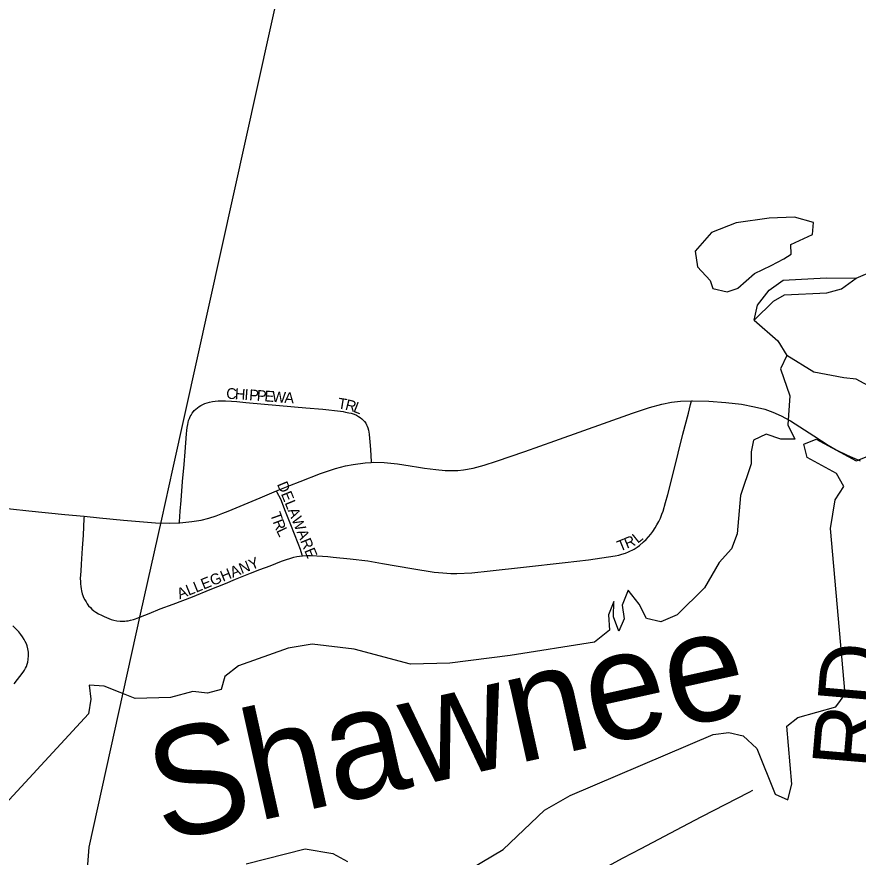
# Model space of a CAD drawing. Extents: x -49 to -8.2, y 9.4 to 23.5.
# Drawn here: x -45.4614 to -45.0943, y 18.5589 to 18.9257 of the extents above; entities that cross this region are included whole.
import ezdxf

# ---------------------------------------------------------------- set-up
doc = ezdxf.new("R2010")
doc.units = 0
for name, color, linetype in [('GM_X_County_Road_Text', 7, 'Continuous'), ('GM_X_Major_Lake', 7, 'Continuous'), ('GM_X_Major_Lake_Text', 7, 'Continuous'), ('GM_X_Major_River', 7, 'Continuous'), ('GM_X_Minor_Lake', 7, 'Continuous'), ('GM_X_Township', 7, 'Continuous'), ('GM_X_Township_Road', 7, 'Continuous'), ('GM_X_Township_Subdivision', 7, 'Continuous'), ('GM_X_Township_Subdivision_Text', 7, 'Continuous')]:
    doc.layers.add(name, color=color, linetype=linetype)

msp = doc.modelspace()

# ---------------------------------------------------------------- linework, layer by layer
at = {"layer": 'GM_X_Major_Lake'}
for points in [[(-45.08824, 18.76383), (-45.09517, 18.76759), (-45.10047, 18.76809), (-45.11368, 18.77065), (-45.12546, 18.77793), (-45.12824, 18.77211), (-45.12414, 18.76026), (-45.125, 18.74756), (-45.12191, 18.74142), (-45.12798, 18.74137), (-45.13437, 18.7436), (-45.13993, 18.74087), (-45.14099, 18.73577), (-45.14092, 18.73065), (-45.14559, 18.71671), (-45.1471, 18.70005), (-45.14952, 18.69346), (-45.15496, 18.68751), (-45.16127, 18.67645), (-45.17328, 18.66476), (-45.18036, 18.66169), (-45.18659, 18.66316), (-45.18986, 18.6693), (-45.19465, 18.67548), (-45.19726, 18.66889), (-45.19645, 18.66299), (-45.19865, 18.65754), (-45.20098, 18.66385), (-45.20083, 18.67049), (-45.20323, 18.66466), (-45.20281, 18.65801), (-45.20937, 18.65284), (-45.24609, 18.64701), (-45.27251, 18.64361), (-45.28958, 18.64322), (-45.31427, 18.64965), (-45.3326, 18.65195), (-45.34307, 18.65009), (-45.36466, 18.6424), (-45.37064, 18.63779), (-45.37228, 18.63214), (-45.37819, 18.63056), (-45.38462, 18.63127), (-45.39435, 18.62864), (-45.40971, 18.62822), (-45.41629, 18.63083), (-45.42324, 18.63364), (-45.42987, 18.63397), (-45.42905, 18.62788), (-45.43014, 18.62146), (-45.47521, 18.57274)], [(-45.10629, 18.70238), (-45.10431, 18.71486), (-45.10057, 18.72065), (-45.10367, 18.72641), (-45.11659, 18.73334), (-45.11798, 18.73925), (-45.11262, 18.74141), (-45.09521, 18.73192), (-45.08966, 18.73408)], [(-45.26775, 18.55129), (-45.24912, 18.56227), (-45.2311, 18.57952), (-45.21997, 18.58591), (-45.15758, 18.61243), (-45.15073, 18.61342), (-45.14451, 18.61196), (-45.13857, 18.60632), (-45.13049, 18.58641), (-45.12504, 18.58402), (-45.12318, 18.59081), (-45.12546, 18.61609), (-45.12064, 18.61997), (-45.10405, 18.62454), (-45.09994, 18.63014), (-45.10629, 18.70238)], [(-45.36128, 18.556), (-45.33554, 18.56265), (-45.32346, 18.56048), (-45.31709, 18.55712)]]:
    msp.add_lwpolyline(points, dxfattribs=at)
at = {"layer": 'GM_X_Major_River'}
for points in [[(-45.09514, 18.81161), (-45.07839, 18.81872)], [(-45.13971, 18.79323), (-45.13824, 18.79984), (-45.13316, 18.80637), (-45.127, 18.81079), (-45.10821, 18.8117), (-45.09514, 18.81161)], [(-45.13971, 18.79323), (-45.13118, 18.80158), (-45.12638, 18.80432), (-45.10798, 18.80525), (-45.10149, 18.807), (-45.09514, 18.81161)], [(-45.13971, 18.79323), (-45.1293, 18.78428), (-45.12544, 18.77792)]]:
    msp.add_lwpolyline(points, dxfattribs=at)
at = {"layer": 'GM_X_Minor_Lake'}
for points in [[(-45.13955, 18.81366), (-45.1323, 18.81716), (-45.12675, 18.82011), (-45.1235, 18.82215), (-45.12362, 18.82633), (-45.11427, 18.83074), (-45.11381, 18.83586), (-45.12211, 18.83826), (-45.13312, 18.83786), (-45.14756, 18.8358), (-45.15824, 18.8316), (-45.16538, 18.82336), (-45.16435, 18.81651), (-45.15894, 18.81054), (-45.15767, 18.80711), (-45.15143, 18.80568), (-45.14667, 18.80732)], [(-45.14673, 18.8073), (-45.13955, 18.81366)]]:
    msp.add_lwpolyline(points, dxfattribs=at)
at = {"layer": 'GM_X_Township'}
for points in [[(-45.45858, 18.19023), (-45.4371, 18.46983), (-45.42991, 18.5633), (-45.40738, 18.66501), (-45.3982, 18.70644), (-45.39337, 18.72821), (-45.30298, 19.13613), (-45.29363, 19.17835), (-45.29186, 19.18634), (-45.28927, 19.19802), (-45.28163, 19.23249), (-45.27701, 19.25333), (-45.23827, 19.42819), (-45.23665, 19.48739)], [(-45.45858, 18.19023), (-45.4371, 18.46983), (-45.42991, 18.5633), (-45.40738, 18.66501), (-45.3982, 18.70644), (-45.39337, 18.72821), (-45.30298, 19.13613), (-45.29363, 19.17835), (-45.29186, 19.18634), (-45.28927, 19.19802), (-45.28163, 19.23249), (-45.27701, 19.25333), (-45.23827, 19.42819), (-45.18647, 19.42522), (-44.37214, 19.37853)]]:
    msp.add_lwpolyline(points, dxfattribs=at)
at = {"layer": 'GM_X_Township_Road'}
for points in [[(-45.30676, 18.73125), (-45.30574, 18.73131), (-45.30115, 18.73113), (-45.29531, 18.7306), (-45.28983, 18.72979), (-45.2862, 18.72919), (-45.28346, 18.72878), (-45.27855, 18.72807), (-45.27453, 18.72771), (-45.27109, 18.72765), (-45.26893, 18.72774), (-45.26645, 18.72799), (-45.26229, 18.72875), (-45.25747, 18.72999), (-45.25215, 18.73172), (-45.23981, 18.73598), (-45.22662, 18.74057), (-45.19269, 18.7527), (-45.18534, 18.75516), (-45.17999, 18.75668), (-45.17577, 18.75752), (-45.17179, 18.75795), (-45.167, 18.75807)], [(-45.167, 18.75807), (-45.16655, 18.75809), (-45.15943, 18.75792), (-45.15201, 18.7574), (-45.14525, 18.75657), (-45.13947, 18.75553), (-45.13499, 18.75441), (-45.1315, 18.75322), (-45.12787, 18.75157), (-45.12384, 18.7493), (-45.11368, 18.74277), (-45.10738, 18.73874), (-45.10386, 18.73673), (-45.09911, 18.73436), (-45.09335, 18.73195)], [(-45.34804, 18.71877), (-45.34232, 18.72112), (-45.33774, 18.72294), (-45.32884, 18.72637), (-45.3224, 18.72851), (-45.31792, 18.72966), (-45.3146, 18.73033), (-45.30941, 18.73107), (-45.30676, 18.73125)], [(-45.3905, 18.70487), (-45.39029, 18.70487), (-45.385, 18.70537), (-45.38098, 18.70603), (-45.37763, 18.70686), (-45.37437, 18.70794), (-45.37148, 18.70907), (-45.36918, 18.70999), (-45.35519, 18.71583), (-45.34804, 18.71877)], [(-45.51521, 18.70597), (-45.51161, 18.7082), (-45.50831, 18.70985), (-45.5049, 18.71123), (-45.50199, 18.71214), (-45.49808, 18.7129), (-45.49412, 18.71335), (-45.49107, 18.71342), (-45.48399, 18.71285), (-45.47566, 18.71201), (-45.46421, 18.71092), (-45.45619, 18.71011), (-45.44047, 18.70855), (-45.43209, 18.7077)], [(-45.43209, 18.7077), (-45.42534, 18.70702), (-45.41479, 18.70601)], [(-45.41479, 18.70601), (-45.40957, 18.70551), (-45.40089, 18.70487), (-45.39497, 18.70473), (-45.3905, 18.70487)]]:
    msp.add_lwpolyline(points, dxfattribs=at)
at = {"layer": 'GM_X_Township_Subdivision'}
for points in [[(-45.3905, 18.70487), (-45.39047, 18.70523), (-45.39009, 18.70992), (-45.38971, 18.71467), (-45.38905, 18.72286), (-45.38843, 18.73036), (-45.38799, 18.73585), (-45.38739, 18.74363), (-45.38726, 18.74513), (-45.38707, 18.74645), (-45.38684, 18.74783), (-45.38666, 18.7487), (-45.38646, 18.7495), (-45.38611, 18.75043), (-45.38572, 18.75123), (-45.38539, 18.75185), (-45.38489, 18.75268), (-45.38438, 18.75341), (-45.38396, 18.75393), (-45.3833, 18.75452), (-45.38261, 18.75508), (-45.38184, 18.75564), (-45.38105, 18.75612), (-45.3803, 18.7565), (-45.37937, 18.75689), (-45.3784, 18.75723), (-45.37729, 18.75752), (-45.37603, 18.75781), (-45.37485, 18.75794), (-45.37353, 18.75804), (-45.37206, 18.75809), (-45.37031, 18.75805), (-45.36778, 18.75794), (-45.36538, 18.75778), (-45.36155, 18.75743), (-45.34673, 18.75607), (-45.33531, 18.75507), (-45.3279, 18.75441), (-45.32021, 18.75357), (-45.31898, 18.75338), (-45.31793, 18.75319), (-45.31654, 18.7529), (-45.31546, 18.75265), (-45.31423, 18.75226), (-45.31318, 18.75178), (-45.31225, 18.7513), (-45.31154, 18.75082), (-45.3109, 18.7503), (-45.31036, 18.74979), (-45.30968, 18.74908), (-45.30918, 18.74837), (-45.30878, 18.74764), (-45.30851, 18.74701), (-45.30829, 18.74626), (-45.308, 18.74524), (-45.30772, 18.74353), (-45.30751, 18.74167), (-45.30738, 18.74034), (-45.30712, 18.73665), (-45.30679, 18.73168), (-45.30676, 18.73125)], [(-45.33674, 18.69045), (-45.33516, 18.69056), (-45.33329, 18.69057), (-45.3305, 18.69044), (-45.328, 18.69029), (-45.32565, 18.69011), (-45.32335, 18.68994), (-45.31599, 18.68918), (-45.30829, 18.68826), (-45.30187, 18.68717), (-45.2891, 18.68486), (-45.27932, 18.68337), (-45.27734, 18.68312), (-45.27554, 18.68299), (-45.27196, 18.6828), (-45.26937, 18.68278), (-45.26289, 18.68308), (-45.25486, 18.68386), (-45.24037, 18.68555), (-45.22216, 18.6876), (-45.21197, 18.68877), (-45.20032, 18.69048), (-45.19868, 18.69081), (-45.19735, 18.69119), (-45.19584, 18.69167), (-45.19448, 18.6922), (-45.19203, 18.69342), (-45.1907, 18.69426), (-45.18977, 18.69494), (-45.1879, 18.69649), (-45.18684, 18.69755), (-45.1858, 18.69868), (-45.18483, 18.69985), (-45.18391, 18.70107), (-45.18285, 18.70265), (-45.18213, 18.70392), (-45.18129, 18.70544), (-45.18059, 18.70687), (-45.17993, 18.70857), (-45.17942, 18.71), (-45.17833, 18.71378), (-45.17738, 18.71716), (-45.1748, 18.72702), (-45.17073, 18.74362), (-45.16839, 18.75267), (-45.1674, 18.75653), (-45.167, 18.75807)], [(-45.33674, 18.69045), (-45.33686, 18.69078), (-45.33769, 18.69317), (-45.33867, 18.69587), (-45.34187, 18.70402), (-45.34416, 18.70979), (-45.34628, 18.71513), (-45.34774, 18.71814), (-45.34804, 18.71877)], [(-45.43209, 18.7077), (-45.43213, 18.70668), (-45.43243, 18.69945), (-45.43286, 18.69379), (-45.43338, 18.68682), (-45.43354, 18.68378), (-45.43371, 18.68054), (-45.43368, 18.6793), (-45.43362, 18.67825), (-45.43354, 18.67706), (-45.43337, 18.67608), (-45.43322, 18.67524), (-45.43288, 18.6739), (-45.43262, 18.67315), (-45.43229, 18.67225), (-45.43177, 18.67123), (-45.43122, 18.67032), (-45.43067, 18.66946), (-45.43006, 18.66868), (-45.42933, 18.66786), (-45.42861, 18.66716), (-45.42785, 18.66648), (-45.42686, 18.6658), (-45.42576, 18.66517), (-45.42451, 18.66454), (-45.42331, 18.66394), (-45.42133, 18.66314), (-45.42028, 18.66272), (-45.41913, 18.66239)], [(-45.41913, 18.66239), (-45.41904, 18.66237), (-45.41784, 18.66214), (-45.41625, 18.66198), (-45.41539, 18.66192), (-45.41422, 18.66198), (-45.41352, 18.66202), (-45.41276, 18.66212), (-45.41177, 18.66233), (-45.41056, 18.66268), (-45.40964, 18.66298), (-45.40748, 18.66385), (-45.40372, 18.66535), (-45.39888, 18.66729), (-45.39317, 18.66943), (-45.38903, 18.671), (-45.38479, 18.6726), (-45.37705, 18.67569), (-45.37037, 18.6784), (-45.36593, 18.68027), (-45.35939, 18.6829), (-45.35541, 18.68443), (-45.35086, 18.68616), (-45.34587, 18.68812), (-45.34379, 18.68885), (-45.34226, 18.68934), (-45.34057, 18.6898), (-45.33923, 18.69012), (-45.338, 18.69032), (-45.33674, 18.69045)], [(-45.46258, 18.63453), (-45.45859, 18.63963), (-45.45801, 18.64057), (-45.45755, 18.64145), (-45.45722, 18.64222), (-45.45692, 18.64313), (-45.45665, 18.64403), (-45.45649, 18.64518), (-45.45632, 18.64691), (-45.45636, 18.64835), (-45.45665, 18.6499), (-45.45693, 18.65112), (-45.45722, 18.65204), (-45.45773, 18.65306), (-45.45817, 18.65397), (-45.45893, 18.65516), (-45.45965, 18.65619), (-45.4606, 18.65732), (-45.4632, 18.65994)], [(-45.21914, 18.54641), (-45.20509, 18.5542), (-45.19687, 18.55859), (-45.18892, 18.5628), (-45.17108, 18.57223), (-45.16255, 18.5767), (-45.14184, 18.58738), (-45.14019, 18.58821)]]:
    msp.add_lwpolyline(points, dxfattribs=at)

# ---------------------------------------------------------------- texts
at = {"layer": 'GM_X_County_Road_Text'}
msp.add_text('RD', height=0.028409, rotation=85.1147, dxfattribs=at).set_placement((-45.08616, 18.59674))
at = {"layer": 'GM_X_Major_Lake_Text'}
msp.add_text('Shawnee', height=0.047347, rotation=12.5169, dxfattribs=at).set_placement((-45.39783, 18.5654))
at = {"layer": 'GM_X_Township_Subdivision_Text'}
for s, height, rotation, p in [('C', 0.00473, 357.887, (-45.37009, 18.75898)), ('H', 0.00473, 355.9969, (-45.36638, 18.75884)), ('I', 0.00473, 355.7119, (-45.36223, 18.75855)), ('P', 0.00473, 355.7348, (-45.36015, 18.7584)), ('P', 0.00473, 355.7348, (-45.35683, 18.75815)), ('E', 0.00473, 355.7348, (-45.3535, 18.7579)), ('W', 0.00473, 355.7388, (-45.35018, 18.75765)), ('A', 0.00473, 355.7337, (-45.34478, 18.75725)), ('T', 0.00473, 350.9734, (-45.3216, 18.7548)), ('R', 0.00473, 345.7163, (-45.31842, 18.7543)), ('L', 0.00473, 338.7212, (-45.31494, 18.75342)), ('DELAWARE', 0.004735, 292.3373, (-45.34796, 18.72174)), ('T', 0.00473, 289.4976, (-45.35097, 18.70862)), ('R', 0.00473, 291.0426, (-45.34981, 18.70534)), ('L', 0.00473, 296.1851, (-45.34828, 18.70143)), ('T', 0.00473, 22.3341, (-45.1983, 18.69224)), ('R', 0.00473, 22.3584, (-45.19521, 18.69351)), ('L', 0.00473, 38.8294, (-45.19049, 18.69568)), ('ALLEGHANY', 0.004735, 22.1657, (-45.39037, 18.67141))]:
    msp.add_text(s, height=height, rotation=rotation, dxfattribs=at).set_placement(p)

doc.saveas('drawing.dxf')
